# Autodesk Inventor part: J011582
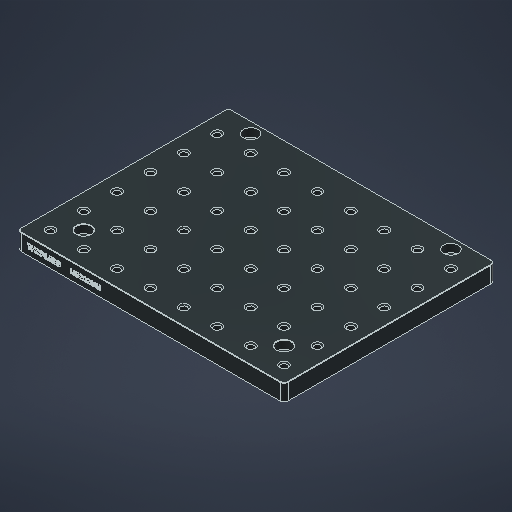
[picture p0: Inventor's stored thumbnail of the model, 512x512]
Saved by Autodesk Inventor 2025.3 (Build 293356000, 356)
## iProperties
RuleStatus: InUse
Created: 2018-01
Project: COMMON
Material: ALUMINUM, 6061-T651
Catalog Web Link: https://www.janelia.org/
Vendor: HHMI: JRC - JET
Document SubType Name: Modeling
Designer: sohna
Density: 2.7 g/cm^3
Appearance: RAL7026_Granite_grey
Description: MB2020 MODDED PLATE
Part Number: J011582
AfterDocSave0: file://Part Number Cleaner
LAB/DEPT: COMMON
REQUESTING SCIENTIST: COMMON
SURFACE ROUGHNESS: N/A
DESIGN DEPARTMENT: HHMI: JRC - ID&F
SPECIAL FINISH: NONE
ALTERED ITEM PART NUMBER: MB2020/M
ALTERED ITEM VENDOR: THORLABS
ALTERED ITEM DESCRIPTION: 200 x 200mm ALUMINUM BREADBOARD
Part Number: MB2020_M - Aluminium Breadboard 200 x 200 x 12.7mm_MB3030_M-1
Revision: ANY
Title: Standard
Author: sohna
Revision Number: -
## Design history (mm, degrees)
feature "Tapped Hole Pattern"
sketch "Sketch1"
  geometry: L1 (0, 199.7)-(194, 199.7) reference; L2 (197, 196.7)-(197, 2.7) reference; L3 (-3, 2.7)-(-3, 196.7) reference; L4 (-3, 157.7)-(197, 157.7); A1 r 3 centre (194, 196.7) between (197, 196.7) and (194, 199.7) reference; A2 r 3 centre (0, 196.7) between (0, 199.7) and (-3, 196.7) reference; 1 further point
  constraints: 2 end point, 2 point on line, 1 perpendicular
  dimensions: "d0" = 42 distance between parallel lines of L4 L1
extrude "Extrusion1" cut sketch "Sketch1" extent not by distance; stored distance "d1" = 0; taper "d2" = 0 deg
sketch "Sketch2"
  geometry: L1 (172, 24.7)-(22, 24.7); L2 (22, 24.7)-(22, 149.7); L3 (22, 149.7)-(172, 149.7); L4 (172, 149.7)-(172, 24.7); C1 r 3.3 at (172, 24.7) reference; C2 r 3.3 at (22, 24.7) reference; 3 further points
  constraints: 8 end point, 3 coincident, 2 parallel, 1 horizontal, 1 perpendicular
  dimensions: "d3" = 125 distance of L3.end L1.start
hole "Hole1" sketch "Sketch2" at (172, 149.7), (22, 149.7) diameter "d4" = 6.6; stored, may be unused: countersink angle "d8" = 81.933 deg, drill point angle "d10" = 118 deg; dims "d5" = 6, "d6" = 11, "d7" = 6, "d9" = 8
fillet "Fillet1" dims "d11" = 3
body "Solid1"
